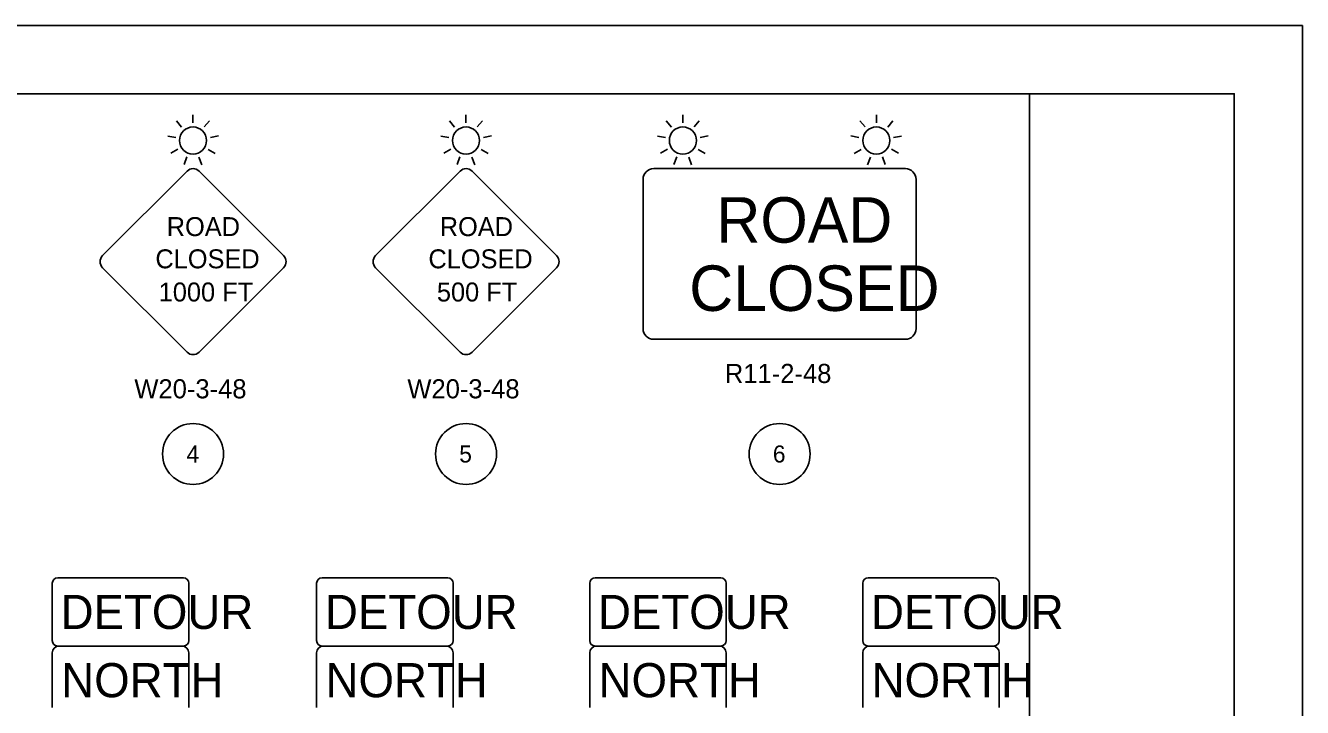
# Model space of a CAD drawing. Extents: x 632.2 to 666.2, y -36.3 to -14.3.
# Drawn here: x 656.83 to 666.19, y -19.3 to -14.3 of the extents above; entities that cross this region are included whole.
import ezdxf

# ---------------------------------------------------------------- set-up
doc = ezdxf.new("R2010")
doc.units = 0
for name, color, linetype in [('Default', 7, 'Continuous'), ('MT_P_Cells', 7, 'Continuous'), ('SH_Border', 7, 'Continuous'), ('SH_Cut_Line', 7, 'Continuous'), ('SN_P_Signs', 7, 'Continuous'), ('SN_P_Text', 7, 'Continuous')]:
    doc.layers.add(name, color=color, linetype=linetype)

msp = doc.modelspace()

# ---------------------------------------------------------------- linework, layer by layer
at = {"layer": 'Default'}
for centre in [(658.0605, -17.4407), (660.0605, -17.4407), (662.3573, -17.4407)]:
    msp.add_circle(centre, 0.2232, dxfattribs=at)
at = {"layer": 'MT_P_Cells'}
for p, q in [((658.0592, -15.0156), (658.0592, -14.9561)), ((660.0592, -15.0156), (660.0592, -14.9561)), ((661.6475, -15.0156), (661.6475, -14.9561)), ((663.0671, -15.0156), (663.0671, -14.9561)), ((657.977, -15.0464), (657.9387, -15.0008)), ((658.1425, -15.045), (658.1808, -14.9994)), ((659.977, -15.0464), (659.9387, -15.0008)), ((660.1425, -15.045), (660.1808, -14.9994)), ((661.5653, -15.0464), (661.527, -15.0008)), ((661.7308, -15.045), (661.769, -14.9994)), ((662.9838, -15.045), (662.9455, -14.9994)), ((663.1493, -15.0464), (663.1876, -15.0008)), ((657.9336, -15.1222), (657.875, -15.1118)), ((658.1874, -15.1217), (658.246, -15.1114)), ((659.9336, -15.1222), (659.875, -15.1118)), ((660.1874, -15.1217), (660.246, -15.1114)), ((661.5219, -15.1222), (661.4633, -15.1118)), ((661.7757, -15.1217), (661.8343, -15.1114)), ((662.9389, -15.1217), (662.8803, -15.1114)), ((663.1927, -15.1222), (663.2513, -15.1118)), ((657.9484, -15.2083), (657.8969, -15.238)), ((658.172, -15.2094), (658.2235, -15.2392)), ((659.9484, -15.2083), (659.8969, -15.238)), ((660.172, -15.2094), (660.2235, -15.2392)), ((661.5367, -15.2083), (661.4852, -15.238)), ((661.7603, -15.2094), (661.8118, -15.2392)), ((662.9543, -15.2094), (662.9028, -15.2392)), ((663.1779, -15.2083), (663.2294, -15.238)), ((658.0152, -15.2652), (657.9948, -15.3212)), ((658.1035, -15.2661), (658.1239, -15.322)), ((660.0152, -15.2652), (659.9948, -15.3212)), ((660.1035, -15.2661), (660.1239, -15.322)), ((661.6035, -15.2652), (661.5831, -15.3212)), ((661.6918, -15.2661), (661.7122, -15.322)), ((663.0228, -15.2661), (663.0024, -15.322)), ((663.1111, -15.2652), (663.1315, -15.3212))]:
    msp.add_line(p, q, dxfattribs=at)
for centre in [(658.0605, -15.1446), (660.0605, -15.1446), (661.6488, -15.1446), (663.0658, -15.1446)]:
    msp.add_circle(centre, 0.0992, dxfattribs=at)
at = {"layer": 'SH_Border'}
msp.add_line((664.1875, -35.8023), (664.1875, -14.8023), dxfattribs=at)
msp.add_lwpolyline([(633.6875, -14.8023), (665.6875, -14.8023), (665.6875, -35.8023), (633.6875, -35.8023)], close=True, dxfattribs=at)
at = {"layer": 'SH_Cut_Line'}
msp.add_lwpolyline([(632.1875, -36.3023), (666.1875, -36.3023), (666.1875, -14.3023), (632.1875, -14.3023)], close=True, dxfattribs=at)
at = {"layer": 'SN_P_Signs'}
for p, q in [((657.0797, -18.8475), (657.9797, -18.8475)), ((659.016, -18.8475), (659.916, -18.8475)), ((661.016, -18.8475), (661.916, -18.8475)), ((663.016, -18.8475), (663.916, -18.8475)), ((657.0297, -19.2975), (657.0297, -18.8975)), ((658.0297, -18.8975), (658.0297, -19.2975)), ((658.966, -19.2975), (658.966, -18.8975)), ((659.966, -18.8975), (659.966, -19.2975)), ((660.966, -19.2975), (660.966, -18.8975)), ((661.966, -18.8975), (661.966, -19.2975)), ((662.966, -19.2975), (662.966, -18.8975)), ((663.966, -18.8975), (663.966, -19.2975))]:
    msp.add_line(p, q, dxfattribs=at)
for points in [[(657.3976, -15.9877), (658.0163, -15.369)], [(658.1047, -15.369), (658.7235, -15.9877)], [(659.3976, -15.9877), (660.0163, -15.369)], [(660.1047, -15.369), (660.7235, -15.9877)], [(661.3573, -15.429), (661.3573, -16.5223)], [(663.279, -15.3507), (661.4356, -15.3507)], [(663.3573, -16.5223), (663.3573, -15.429)], [(658.0163, -16.6948), (657.3976, -16.0761)], [(658.7235, -16.0761), (658.1047, -16.6948)], [(660.0163, -16.6948), (659.3976, -16.0761)], [(660.7235, -16.0761), (660.1047, -16.6948)], [(661.4356, -16.6007), (663.279, -16.6007)], [(657.0297, -18.3875), (657.0297, -18.8075)], [(657.9897, -18.3475), (657.0697, -18.3475)], [(658.0297, -18.8075), (658.0297, -18.3875)], [(658.966, -18.3875), (658.966, -18.8075)], [(659.926, -18.3475), (659.006, -18.3475)], [(659.966, -18.8075), (659.966, -18.3875)], [(660.966, -18.3875), (660.966, -18.8075)], [(661.926, -18.3475), (661.006, -18.3475)], [(661.966, -18.8075), (661.966, -18.3875)], [(662.966, -18.3875), (662.966, -18.8075)], [(663.926, -18.3475), (663.006, -18.3475)], [(663.966, -18.8075), (663.966, -18.3875)], [(657.0697, -18.8475), (657.9897, -18.8475)], [(659.006, -18.8475), (659.926, -18.8475)], [(661.006, -18.8475), (661.926, -18.8475)], [(663.006, -18.8475), (663.926, -18.8475)]]:
    msp.add_lwpolyline(points, dxfattribs=at)
for centre, radius, start, end in [((658.0605, -15.4132), 0.0625, 45, 135), ((660.0605, -15.4132), 0.0625, 45, 135), ((661.4356, -15.429), 0.0783, 90, 180), ((663.279, -15.429), 0.0783, 0, 90), ((657.4418, -16.0319), 0.0625, 135, 225), ((658.6793, -16.0319), 0.0625, 315, 45), ((659.4418, -16.0319), 0.0625, 135, 225), ((660.6793, -16.0319), 0.0625, 315, 45), ((661.4356, -16.5223), 0.0783, 180, 270), ((663.279, -16.5223), 0.0783, 270, 0), ((658.0605, -16.6506), 0.0625, 225, 315), ((660.0605, -16.6506), 0.0625, 225, 315), ((657.0697, -18.3875), 0.04, 90, 180), ((657.9897, -18.3875), 0.04, 0, 90), ((659.006, -18.3875), 0.04, 90, 180), ((659.926, -18.3875), 0.04, 0, 90), ((661.006, -18.3875), 0.04, 90, 180), ((661.926, -18.3875), 0.04, 0, 90), ((663.006, -18.3875), 0.04, 90, 180), ((663.926, -18.3875), 0.04, 0, 90), ((657.0697, -18.8075), 0.04, 180, 270), ((657.0797, -18.8975), 0.05, 90, 180), ((657.9797, -18.8975), 0.05, 0, 90), ((657.9897, -18.8075), 0.04, 270, 0), ((659.006, -18.8075), 0.04, 180, 270), ((659.016, -18.8975), 0.05, 90, 180), ((659.916, -18.8975), 0.05, 0, 90), ((659.926, -18.8075), 0.04, 270, 0), ((661.006, -18.8075), 0.04, 180, 270), ((661.016, -18.8975), 0.05, 90, 180), ((661.916, -18.8975), 0.05, 0, 90), ((661.926, -18.8075), 0.04, 270, 0), ((663.006, -18.8075), 0.04, 180, 270), ((663.016, -18.8975), 0.05, 90, 180), ((663.916, -18.8975), 0.05, 0, 90), ((663.926, -18.8075), 0.04, 270, 0)]:
    msp.add_arc(centre, radius, start, end, dxfattribs=at)

# ---------------------------------------------------------------- texts
at = {"layer": 'Default'}
for s, p in [('4', (658.013, -17.5032)), ('5', (660.0106, -17.5032)), ('6', (662.3078, -17.5032))]:
    msp.add_text(s, height=0.125, dxfattribs=at).set_placement(p)
at = {"layer": 'SN_P_Signs'}
for s, height, p in [('ROAD', 0.33333, (661.895, -15.8929)), ('ROAD', 0.1389, (657.8679, -15.8446)), ('ROAD', 0.1389, (659.8679, -15.8446)), ('CLOSED', 0.1389, (657.7848, -16.0806)), ('CLOSED', 0.1389, (659.7848, -16.0806)), ('CLOSED', 0.33333, (661.6956, -16.3929)), ('1000 FT', 0.1389, (657.809, -16.3236)), ('500 FT', 0.1389, (659.8468, -16.3236)), ('DETOUR', 0.25, (657.0905, -18.7225)), ('DETOUR', 0.25, (659.0268, -18.7225)), ('DETOUR', 0.25, (661.0268, -18.7225)), ('DETOUR', 0.25, (663.0268, -18.7225)), ('NORTH', 0.25, (657.095, -19.2225)), ('NORTH', 0.25, (659.0313, -19.2225)), ('NORTH', 0.25, (661.0313, -19.2225)), ('NORTH', 0.25, (663.0313, -19.2225))]:
    msp.add_text(s, height=height, dxfattribs=at).set_placement(p)
at = {"layer": 'SN_P_Text'}
for s, p in [('R11-2-48', (661.9562, -16.9207)), ('W20-3-48', (657.6305, -17.0331)), ('W20-3-48', (659.6305, -17.0331))]:
    msp.add_text(s, height=0.14, dxfattribs=at).set_placement(p)

doc.saveas('drawing.dxf')
